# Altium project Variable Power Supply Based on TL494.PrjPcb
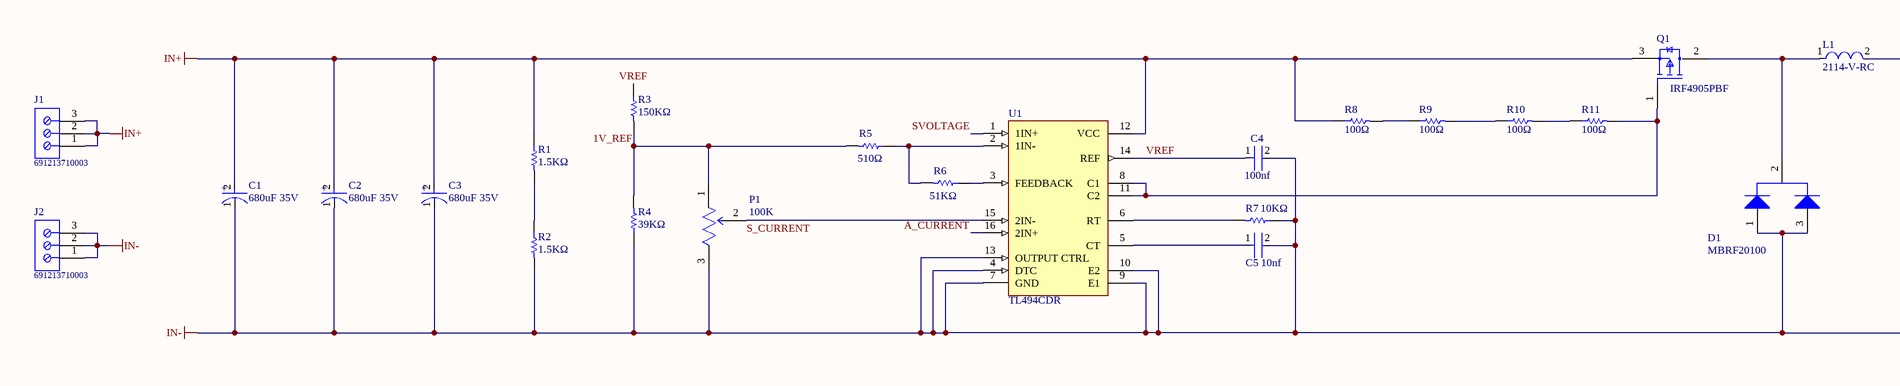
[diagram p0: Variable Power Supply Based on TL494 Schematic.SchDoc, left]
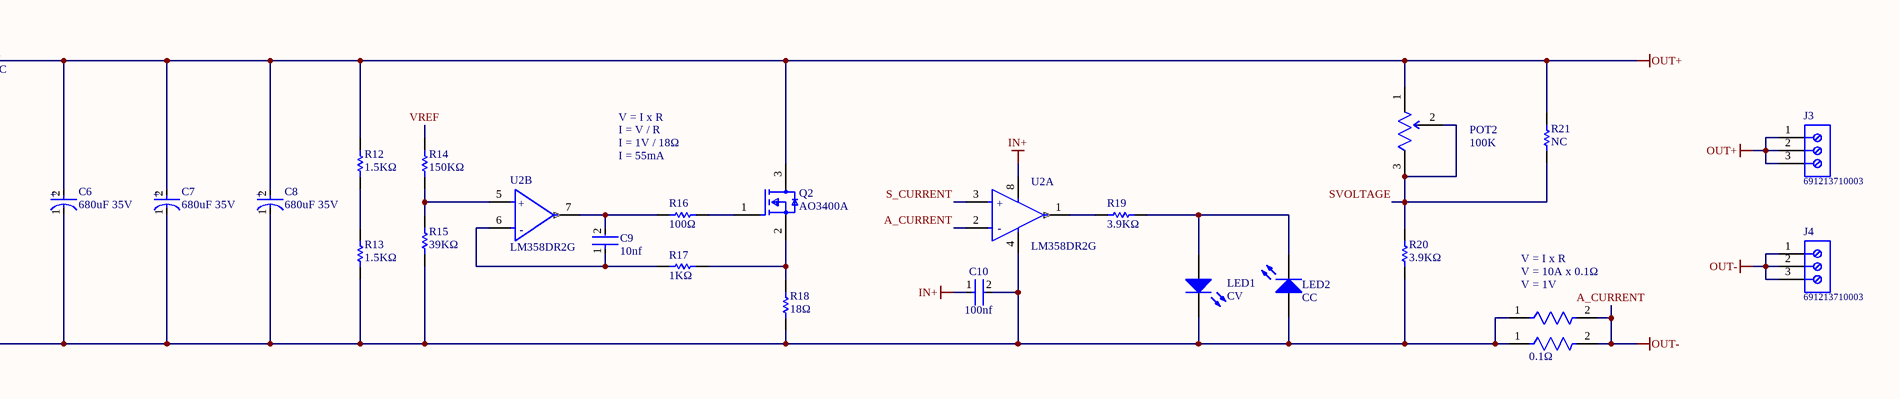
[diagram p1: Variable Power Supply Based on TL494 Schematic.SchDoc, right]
1 sheet, 47 parts. Net scope: global (net labels, ports and power ports of the same name join across sheets).
Board file: Variable Power Supply Based on TL494 PCB.PcbDoc

## Sheet Variable Power Supply Based on TL494 Schematic.SchDoc
size 762 x 86 mm; SheetNumber: 1; SheetTotal: 1

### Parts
C1  680uF 35V  [FP-EEU-FM1V681B-MFG]
C2  680uF 35V  [FP-EEU-FM1V681B-MFG]
C3  680uF 35V  [FP-EEU-FM1V681B-MFG]
C4  100nf  [FP-C0805C-DG-MFG]
C5  10nf  [FP-C0805C-DG-MFG]
C6  680uF 35V  [FP-EEU-FM1V681B-MFG]
C7  680uF 35V  [FP-EEU-FM1V681B-MFG]
C8  680uF 35V  [FP-EEU-FM1V681B-MFG]
C9  10nf  [FP-C0805C-DG-MFG]
C10  100nf  [FP-C0805C-DG-MFG]
D1  MBRF20100  [ONSC-TO-220FP-3-221D-03]
J1  691213710003  [691213710003]
J2  691213710003  [691213710003]
J3  691213710003  [691213710003]
J4  691213710003  [691213710003]
L1  2114-V-RC  [FP-2114-V-RC-MFG]
LED1  CV  [1206_A]
LED2  CC  [1206_A]
P1  100K  [FP-3296W-MFG]
POT2  100K  [FP-3296W-MFG]
Q1  IRF4905PBF  [FP-T14-0413-MFG]
Q2  AO3400A  [FP-SOT23-MFG]
R1  1.5KΩ  [RESC3216X60X45ML15T20]
R2  1.5KΩ  [RESC3216X60X45ML15T20]
R3  150KΩ  [RESC2013X60X35ML10T20]
R4  39KΩ  [RESC2013X60X35ML10T20]
R5  510Ω  [RESC2013X60X35ML10T20]
R6  51KΩ  [RESC2013X60X35ML10T20]
R7  10KΩ  [RESC2013X60X35ML10T20]
R8  100Ω  [RESC2013X60X35ML10T20]
R9  100Ω  [RESC2013X60X35ML10T20]
R10  100Ω  [RESC2013X60X35ML10T20]
R11  100Ω  [RESC2013X60X35ML10T20]
R12  1.5KΩ  [RESC3216X60X45ML15T20]
R13  1.5KΩ  [RESC3216X60X45ML15T20]
R14  150KΩ  [RESC2013X60X35ML10T20]
R15  39KΩ  [RESC2013X60X35ML10T20]
R16  100Ω  [RESC2013X60X35ML10T20]
R17  1KΩ  [RESC2013X60X35ML10T20]
R18  18Ω  [RESC3216X60X45ML15T20]
R19  3.9KΩ  [RESC2013X60X35ML10T20]
R20  3.9KΩ  [RESC2013X60X35ML10T20]
R21  NC  [RESC2013X60X35ML10T20]
RS1  0.1Ω  [FP-20-MFG]  (value not drawn)
RS2  0.1Ω  [FP-20-MFG]
U1  TL494CDR  [D0016A_N]
U2  LM358DR2G  [FP-751-07-IPC_C]  (parts A,B of 2)

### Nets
A_CURRENT: J4.1 J4.2 J4.3 RS1.2 RS2.2 U1.16(2IN+) U2.2(INPUT_A-)  [also labelled OUT-]
IN+: C1.2(A) C2.2(A) C3.2(A) C10.1 J1.1 J1.2 J1.3 Q1.3(S) R1.1 R8.1 U1.12(VCC) U2.8(VCC)
IN-: C1.1(C) C2.1(C) C3.1(C) C4.2 C5.2 C6.1(C) C7.1(C) C8.1(C) C10.2 D1.1(A1) D1.3(A2) J2.1 J2.2 J2.3 LED1.1(K) LED2.2(A) P1.3(CW) R2.2 R4.1 R7.1 R13.2 R15.1 R18.2 R20.2 RS1.1 RS2.1 U1.4(DTC) U1.7(GND) U1.9(E1) U1.10(E2) U1.13(OUTPUT_CTRL) U2.4(VEE/GND)
OUT+: C6.2(A) C7.2(A) C8.2(A) J3.1 J3.2 J3.3 L1.2 POT2.1(CCW) Q2.3(D) R12.1 R21.1
1V_REF: P1.1(CCW) R3.2 R4.2 R5.2
S_CURRENT: P1.2(WIPER) U1.15(2IN-) U2.3(INPUT_A+)
SVOLTAGE: POT2.2(WIPER) POT2.3(CW) R20.1 R21.2 U1.1(1IN+)
VREF: C4.1 R3.1 R14.2 U1.14(REF)
NetC5_1: C5.1 U1.5(CT)
NetC9_1: C9.1 R17.2 U2.6(INPUT_B-)
NetC9_2: C9.2 R16.2 U2.7(OUTPUT_B)
NetD1_2: D1.2(K) L1.1 Q1.2(D)
NetLED1_2: LED1.2(A) LED2.1(K) R19.1
NetQ1_1: Q1.1(G) R11.2 U1.8(C1) U1.11(C2)
NetQ2_1: Q2.1(G) R16.1
NetQ2_2: Q2.2(S) R17.1 R18.1
NetR1_2: R1.2 R2.1
NetR5_1: R5.1 R6.2 U1.2(1IN-)
NetR6_1: R6.1 U1.3(FEEDBACK)
NetR7_2: R7.2 U1.6(RT)
NetR8_2: R8.2 R9.1
NetR9_2: R9.2 R10.1
NetR10_2: R10.2 R11.1
NetR12_2: R12.2 R13.1
NetR14_1: R14.1 R15.2 U2.5(INPUT_B+)
NetR19_2: R19.2 U2.1(OUTPUT_A)

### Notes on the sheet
- V = I x R
- I = V / R
- I = 1V / 18Ω
- I = 55mA
- (near RS1) V = 10A x 0.1Ω
- (near RS1) V = 1V

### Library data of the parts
C1-C3 C6-C8 = CMP-05427-000051-1: CAP ALUM 680UF 20% 35V RADIAL; Polarity: Polar; Dissipation Factor: 0.12%; Impedance: 18mR; Life (Hours): 5000Hour; Lead Diameter: 0.6mm; Ripple Current: 2.6A
C4 C5 C9 C10 = CMP-2007-03243-2: General Purpose Ceramic Capacitor, 0805, 10nF, 50V; Manufacturer Part Number: C0805C106K8PACTU; Manufacturer: Kemet; 3DS Part Number: 220-00001; Tolerance: 10%; Capacitance: 10uF; Value: 10uF; Temperature Coefficient: 15%; Voltage: 10V; Temperature Characteristic: X5R
D1 = CMP-1055-00696-1: SWITCHMODE(TM) Schottky Power Rectifier, 3-Pin TO-220FP, Pb-Free, Tube; PartNumber: MBRF20100CTG; Manufacturer: On Semiconductor; IFSM Max (A): 150; Configuration: Common Cathode
J1-J4 = CMP-1502-02527-1: Serie 213 - 5.00 mm Horizontal Entry Modular with RisingCage Clamp WR-TBL, 3 pin; Manufacturer: Wurth Elektronik; Pin Number: 3; Pitch: 5.00mm
L1 = CMP-07248-000012-1: FIXED IND 150UH 3.4A 62 MOHM TH; Manufacturer: Bourns; Tolerance: 15%; Test Frequency: 1kHz; Shielding: true; Series Resistance: 0.062Ω
LED1 LED2 = CMP-1426-00015-1: SMD mono-color Chip LED, WL-SMCW, Blue; Manufacturer: Wuerth Elektronik; PartNumber: 150120BS75000
P1 = CMP-07234-000024-1: TRIMMER 10K OHM 0.5W PC PIN TOP; Resistance: 10kR; Temperature Coefficient: 100ppm/°C; Power Rating: 500mW; Tolerance: 10%; Number of Turns: 25
POT2 = CMP-07234-000024-1: TRIMMER 100K OHM 0.5W PC PIN TOP; Resistance: 10kR; Temperature Coefficient: 100ppm/°C; Power Rating: 500mW; Tolerance: 10%; Number of Turns: 25
Q1 = CMP-02550-000110-1: MOSFET P-CH 55V 74A TO-220AB; Manufacturer: Vishay; Manufacturer Part Number: SUP90P06-09L-E3; Pulse Drain Current: -200A; Turn Off Delay Time: 140ns; Depletion Mode: False; Standoff Height: 3.32mm; Turn On Delay Time: 20ns; Typ Forward Diode Voltage: -1V; Gate To Source Voltage: 20V; Reverse Recovery Charge: 90nC; Input Capacitace At Vds: 9200pF @ -25V; Continuous Drain Current: -90A; Drain To Source Voltage: -60V; Max Forward Diode Voltage: -1.5V; Gate Charge At Vgs: 160nC @ -10V; Max Junction Temp: +175°C; Drain To Source Resistance: 0.0074Ω; Power Dissipation: 2.4W; Threshold Vgs Max: -3V; Rthja Max: 62°C/W; Number Of P Channels: 1; Reverse Recovery Time: 60ns
Q2 = CMP-83955-000006-1: MOSFET N-CH 30V 5.7A SOT23; Input Capacitance: 630pF; Number of Elements: 1; Rds On Max: 26.5mR; Max Power Dissipation: 1.4W; Gate to Source Voltage (Vgs): 12V
R1 R2 R12 R13 = CMP-2100-03616-1: Thick Film Resistors, 1206, 1.5KΩ, 1%, 0.125W; Manufacturer: Vishay Semiconductor; Power Rating: 250mW; Voltage Rating (DC): 200V; Resistance: 1KOhm; Temperature Coefficient: 100ppm/degreesC
R3 R14 = CMP-2100-03673-1: Thick Film Resistors, 0805, 150KΩ, 5%, 0.125W; Manufacturer: Yageo; Power Rating: 125mW; Resistance: 0mOhm; Voltage Rating (DC): 150V; Temperature Coefficient: 200ppm/degreesC
R4 R15 = CMP-2100-03673-1: Thick Film Resistors, 0805, 39KΩ, 5%, 0.125W; Manufacturer: Yageo; Power Rating: 125mW; Resistance: 0mOhm; Voltage Rating (DC): 150V; Temperature Coefficient: 200ppm/degreesC
R5 = CMP-2100-03673-1: Thick Film Resistors, 0805, 510Ω, 5%, 0.125W; Manufacturer: Yageo; Power Rating: 125mW; Resistance: 0mOhm; Voltage Rating (DC): 150V; Temperature Coefficient: 200ppm/degreesC
R6 = CMP-2100-03673-1: Thick Film Resistors, 0805, 51kΩ, 5%, 0.125W; Manufacturer: Yageo; Power Rating: 125mW; Resistance: 0mOhm; Voltage Rating (DC): 150V; Temperature Coefficient: 200ppm/degreesC
R7-R11 = CMP-2100-03673-1: Thick Film Resistors, 0805, 10kΩ, 5%, 0.125W; Manufacturer: Yageo; Power Rating: 125mW; Resistance: 0mOhm; Voltage Rating (DC): 150V; Temperature Coefficient: 200ppm/degreesC
R16 = CMP-2100-03673-1: Thick Film Resistors, 0805, 100Ω, 5%, 0.125W; Manufacturer: Yageo; Power Rating: 125mW; Resistance: 0mOhm; Voltage Rating (DC): 150V; Temperature Coefficient: 200ppm/degreesC
R17 = CMP-2100-03673-1: Thick Film Resistors, 0805, 1KΩ, 5%, 0.125W; Manufacturer: Yageo; Power Rating: 125mW; Resistance: 0mOhm; Voltage Rating (DC): 150V; Temperature Coefficient: 200ppm/degreesC
R18 = CMP-2100-03616-1: Thick Film Resistors, 1206, 18Ω, 1%, 0.125W; Manufacturer: Vishay Semiconductor; Power Rating: 250mW; Voltage Rating (DC): 200V; Resistance: 1KOhm; Temperature Coefficient: 100ppm/degreesC
R19 R20 = CMP-2100-03673-1: Thick Film Resistors, 0805, 3.9KΩ, 5%, 0.125W; Manufacturer: Yageo; Power Rating: 125mW; Resistance: 0mOhm; Voltage Rating (DC): 150V; Temperature Coefficient: 200ppm/degreesC
R21 = CMP-2100-03673-1: Thick Film Resistors, 0805, NC, 5%, 0.125W; Manufacturer: Yageo; Power Rating: 125mW; Resistance: 0mOhm; Voltage Rating (DC): 150V; Temperature Coefficient: 200ppm/degreesC
RS1 RS2 = CMP-33362-000002-1: RES 20K OHM 10W 5% AXIAL; Manufacturer Part Number: 20J20K; Manufacturer: Ohmite; Value: 20000Ω; Temperature Coefficient: 30ppm/°C; Voltage Rating: 720V
U1 = CMP-0319-00950-2: Pulse-Width-Modulation Control Circuit with Voltage Control, 45 % Duty Cycle, 0 to +70 degC, 16-pin SOIC (D), Green (RoHS & no Sb/Br); Manufacturer: Texas Instruments; Regulated Outputs(#): 2; Frequency(Max)(kHz): 300; Topology: Boost, Buck, Flyback, Forward, Full-Bridge, Half-Bridge, Push-Pull; SubFamily: PWM Controller; Duty Cycle(Max)(%): 45; Rating: Military
U2 = CMP-1310-00291-2: IC OPAMP GP 2 CIRCUIT 8SOIC; Gain Bandwidth Product: 1MHz; Number of Circuits: 2; Min Supply Voltage: 3V; Slew Rate: 0.6V/µs; Max Dual Supply Voltage: 16V; Common Mode Rejection Ratio: 65dB; Input Bias Current: 250nA; Min Dual Supply Voltage: 1.5V; Dual Supply Voltage: 9V; Operating Supply Current: 1.5mA; Output Current: 40mA; Input Offset Voltage (Vos): 7mV; Nominal Supply Current: 1.2mA; Voltage Gain: 100dB; Max Supply Voltage: 32V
